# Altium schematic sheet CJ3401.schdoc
size 127 x 101 mm
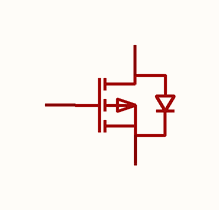
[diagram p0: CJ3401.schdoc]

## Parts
Q?  cj3401  [SOT-23-3_L2.9-W1.6-P1.90-LS2.8-BR]  (value not drawn)

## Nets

Not connected (* = marked no-connect by the designer): Q? 1(G) 2(S) 3(D)

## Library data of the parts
Q? = cj3401: 数量:1个P沟道;漏源电压(Vdss):30V;连续漏极电流(Id):4.2A;导通电阻(RDS(on)):65mΩ@10V;耗散功率(Pd):350mW;阈值电压(Vgs(th)):1.3V;; Manufacturer: CJ(江苏长电/长晶); AddInBom: yes; ModelId: 89cb27a44ab2466697082bb9fd73a7d0; ModelName: SOT-23-3L_L2.9-W1.6-H1.1-LS2.8-P0.95; ModelTransform: 114.173,110.236,0,90,0,0,0,0,0; Number: 1个P沟道; Drain to Source Voltage: 30V; Current - Continuous Drain(Id): 4.2A; Pd - Power Dissipation: 350mW; Gate Threshold Voltage (Vgs(th)): 1.3V; Input Capacitance(Ciss): 954pF; Reverse Transfer Capacitance (Crss@Vds): 77pF; Type: P沟道; Output Capacitance(Coss): 115pF; Vgs: ±12V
